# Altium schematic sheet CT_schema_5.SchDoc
size 334 x 183 mm
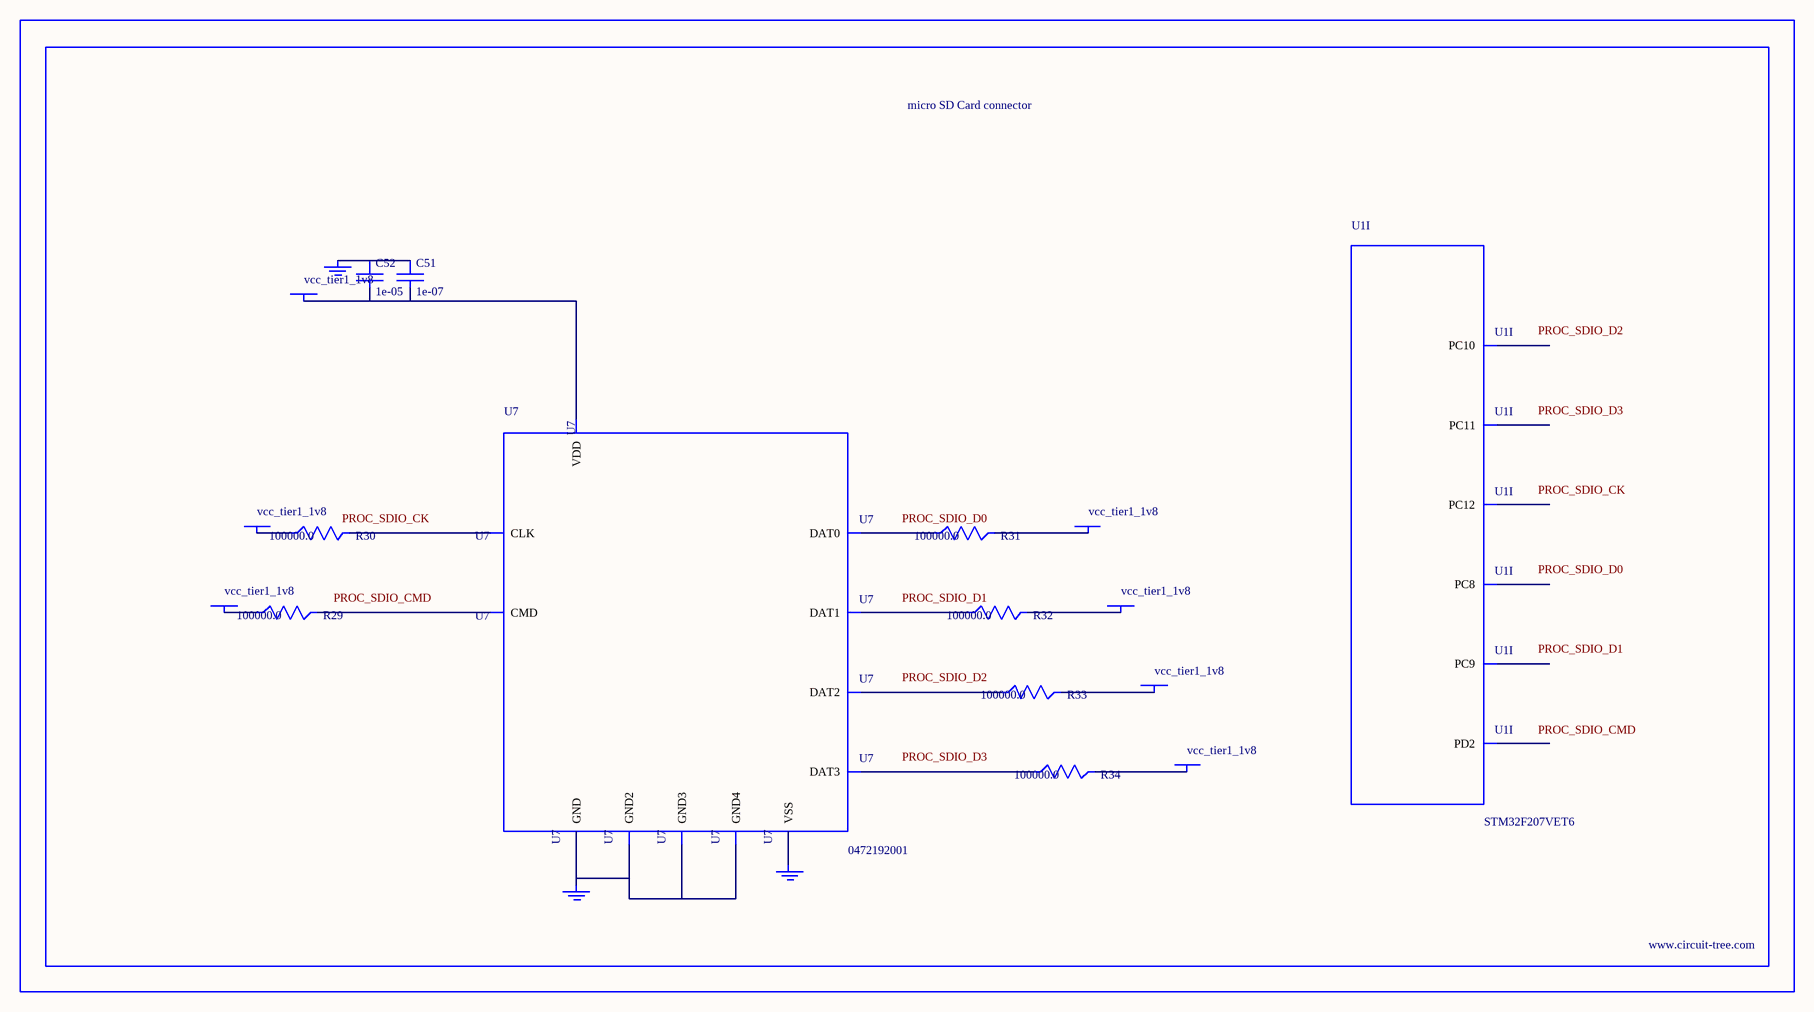
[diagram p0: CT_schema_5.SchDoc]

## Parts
BORDER4  (no value)
C51  1e-07  [C0402]
C52  1e-05  [C0805]
GND_INSTANCE_4_0  (no value)
GND_INSTANCE_4_1  (no value)
GND_INSTANCE_4_2  (no value)
POWER_INSTANCE_4_0  vcc_tier1_1v8
POWER_INSTANCE_4_1  vcc_tier1_1v8
POWER_INSTANCE_4_2  vcc_tier1_1v8
POWER_INSTANCE_4_3  vcc_tier1_1v8
POWER_INSTANCE_4_4  vcc_tier1_1v8
POWER_INSTANCE_4_5  vcc_tier1_1v8
POWER_INSTANCE_4_6  vcc_tier1_1v8
R29  100000.0  [R0603]
R30  100000.0  [R0603]
R31  100000.0  [R0603]
R32  100000.0  [R0603]
R33  100000.0  [R0603]
R34  100000.0  [R0603]
U1  STM32F207VET6  [LQFP100]  (part I of 9)
U7  0472192001  [MOLEX_47219-2001]

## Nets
NetC51_1: C51.1 C52.1 GND_INSTANCE_4_0.0(GND)
NetC51_2: C51.2 C52.2 POWER_INSTANCE_4_3.0(PWR) U7.4(VDD)
NetGND_INSTANCE_4_1_0: GND_INSTANCE_4_1.0(GND) U7.6(VSS)
NetGND_INSTANCE_4_2_0: GND_INSTANCE_4_2.0(GND) U7.G1(GND) U7.G2(GND2) U7.G3(GND3) U7.G4(GND4)
NetPOWER_INSTANCE_4_0_0: POWER_INSTANCE_4_0.0(PWR) R33.2
NetPOWER_INSTANCE_4_1_0: POWER_INSTANCE_4_1.0(PWR) R34.2
NetPOWER_INSTANCE_4_2_0: POWER_INSTANCE_4_2.0(PWR) R29.1
NetPOWER_INSTANCE_4_4_0: POWER_INSTANCE_4_4.0(PWR) R30.1
NetPOWER_INSTANCE_4_5_0: POWER_INSTANCE_4_5.0(PWR) R31.2
NetPOWER_INSTANCE_4_6_0: POWER_INSTANCE_4_6.0(PWR) R32.2
NetR29_2: R29.2 U7.3(CMD)
NetR30_2: R30.2 U7.5(CLK)
NetR31_1: R31.1 U7.7(DAT0)
NetR32_1: R32.1 U7.8(DAT1)
NetR33_1: R33.1 U7.1(DAT2)
NetR34_1: R34.1 U7.2(DAT3)

Not connected (* = marked no-connect by the designer): U1 65(PC8) 66(PC9) 78(PC10) 79(PC11) 80(PC12) 83(PD2)

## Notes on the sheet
- Labels drawn without touching a wire or pin: PROC_SDIO_CK, PROC_SDIO_CMD, PROC_SDIO_D0, PROC_SDIO_D1, PROC_SDIO_D2, PROC_SDIO_D3

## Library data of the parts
BORDER4 = BORDER_PAGE4
C51 = C0402C104K3RACTU
C52 = C0805C106K8RACTU
GND_INSTANCE_4_0-GND_INSTANCE_4_2 = GND
POWER_INSTANCE_4_0-POWER_INSTANCE_4_6 = PWR
R29-R34 = RC0603JR-07100KL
